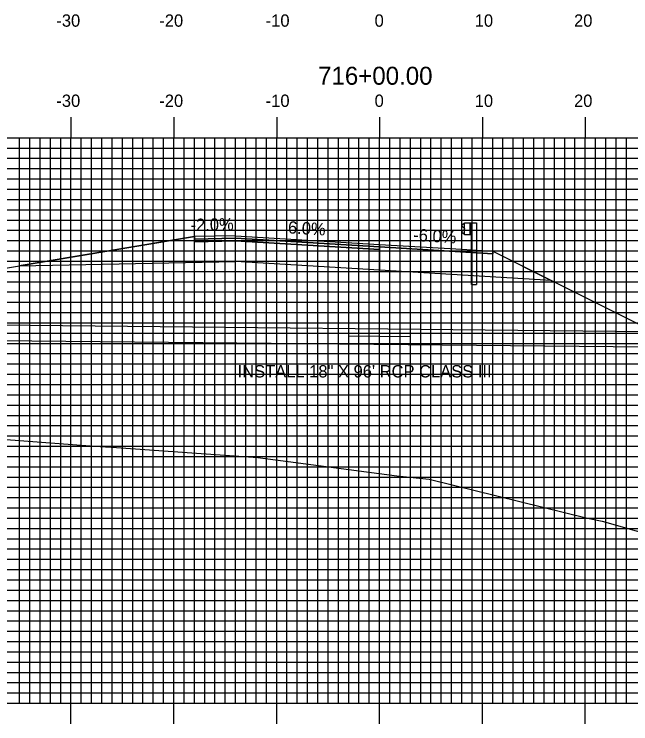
# Model space of a CAD drawing. Extents: x 856478 to 856821, y 364366 to 364586.
# Drawn here: x 856607.8 to 856667.7, y 364448.1 to 364517.1 of the extents above; entities that cross this region are included whole.
import ezdxf

# ---------------------------------------------------------------- set-up
doc = ezdxf.new("R2010")
doc.units = 0
for name, color, linetype in [('ANNOTATION', 7, 'Continuous'), ('D_Drainage_Culvert', 7, 'Continuous'), ('D_Drainage_Text', 7, 'Continuous'), ('D_Guardrail_Beam_Rt', 7, 'Continuous'), ('D_Roadway_Edge_Shoulder', 7, 'Continuous'), ('D_Roadway_Edge_TW', 7, 'Continuous'), ('D_Roadway_Pavement', 7, 'Continuous'), ('D_Roadway_SlopeLines', 7, 'Continuous'), ('D_Roadway_SubGrade', 7, 'Continuous'), ('H_V ANNOTATION', 7, 'Continuous'), ('MAJOR', 7, 'Continuous'), ('MINOR', 7, 'Continuous'), ('S_Roadway_Centerline', 7, 'Continuous')]:
    doc.layers.add(name, color=color, linetype=linetype)

msp = doc.modelspace()

# ---------------------------------------------------------------- linework, layer by layer
at = {"layer": 'ANNOTATION'}
msp.add_line((856582.323, 364488.315), (856625.309, 364495.474), dxfattribs=at)
at = {"layer": 'D_Drainage_Culvert'}
for p, q in [((856577.032, 364487.162), (856673.027, 364486.202)), ((856577.017, 364485.662), (856673.012, 364484.702)), ((856640.309, 364485.817), (856646.309, 364485.757))]:
    msp.add_line(p, q, dxfattribs=at)
at = {"layer": 'D_Guardrail_Beam_Rt'}
for p, q in [((856651.49, 364496.712), (856651.347, 364496.612)), ((856651.347, 364496.469), (856651.542, 364496.333)), ((856651.58, 364496.734), (856651.506, 364496.719)), ((856651.58, 364496.817), (856652.268, 364496.817)), ((856651.58, 364495.65), (856651.58, 364496.817)), ((856652.101, 364496.817), (856652.101, 364495.65)), ((856652.205, 364496.817), (856652.205, 364495.65)), ((856652.268, 364496.817), (856652.738, 364496.817)), ((856652.268, 364496.817), (856652.268, 364495.65)), ((856652.738, 364496.817), (856652.738, 364490.817)), ((856651.542, 364496.134), (856651.347, 364495.998)), ((856651.347, 364495.855), (856651.49, 364495.755)), ((856651.506, 364495.748), (856651.58, 364495.734)), ((856651.576, 364496.269), (856651.576, 364496.199)), ((856652.268, 364495.65), (856651.58, 364495.65)), ((856652.247, 364490.817), (856652.247, 364495.65)), ((856652.247, 364490.817), (856652.738, 364490.817))]:
    msp.add_line(p, q, dxfattribs=at)
for centre, major_axis, start_param, end_param in [((856651.397, 364496.541), (-0.0877, 0), 5.323254, 7.243116), ((856651.514, 364496.678), (-0.0417, 0), 4.907132, 5.323254), ((856651.497, 364496.269), (0.0789, 0), 0, 0.959931), ((856651.397, 364495.927), (-0.0877, 0), 5.323254, 7.243116), ((856651.514, 364495.789), (-0.0417, 0), 0.959931, 1.376053), ((856651.497, 364496.199), (0.0789, 0), 5.323254, 6.283185)]:
    msp.add_ellipse(centre, major_axis=major_axis, ratio=0.995501, start_param=start_param, end_param=end_param, dxfattribs=at)
at = {"layer": 'D_Roadway_Edge_Shoulder'}
for points in [[(856629.309, 364495.554), (856625.309, 364495.474), (856625.309, 364495.224), (856629.309, 364495.304)], [(856643.309, 364494.714), (856651.309, 364494.234), (856651.309, 364494.234), (856654.309, 364494.054), (856654.309, 364493.804), (856643.309, 364494.464)]]:
    msp.add_lwpolyline(points, close=True, dxfattribs=at)
at = {"layer": 'D_Roadway_Edge_TW'}
msp.add_lwpolyline([(856629.309, 364495.554), (856643.309, 364494.714), (856643.309, 364494.464), (856629.309, 364495.304)], close=True, dxfattribs=at)
at = {"layer": 'D_Roadway_Pavement'}
for points in [[(856629.309, 364495.304), (856625.309, 364495.224), (856625.309, 364494.974), (856629.309, 364495.054)], [(856629.309, 364495.304), (856643.309, 364494.464), (856643.309, 364494.214), (856629.309, 364495.054)]]:
    msp.add_lwpolyline(points, close=True, dxfattribs=at)
msp.add_lwpolyline([(856643.309, 364494.464), (856643.309, 364494.214)], dxfattribs=at)
msp.add_lwpolyline([(856643.309, 364494.464), (856643.309, 364494.214)], dxfattribs=at)
at = {"layer": 'D_Roadway_SlopeLines'}
msp.add_lwpolyline([(856654.309, 364494.054), (856726.292, 364458.062)], dxfattribs=at)
at = {"layer": 'D_Roadway_SubGrade'}
for points in [[(856629.309, 364495.054), (856625.309, 364494.974), (856625.309, 364495.224), (856625.309, 364495.474), (856608.264, 364492.633), (856629.309, 364493.054)], [(856629.309, 364495.054), (856643.309, 364494.214), (856643.309, 364492.214), (856629.309, 364493.054)], [(856643.309, 364494.214), (856643.309, 364494.464), (856654.309, 364493.804), (856654.309, 364494.054), (856659.991, 364491.213), (856643.309, 364492.214)]]:
    msp.add_lwpolyline(points, close=True, dxfattribs=at)
at = {"layer": 'MAJOR'}
for p, q in [((856613.309, 364507.086), (856613.309, 364505.082)), ((856623.309, 364507.086), (856623.309, 364505.082)), ((856633.309, 364507.086), (856633.309, 364505.082)), ((856643.309, 364507.086), (856643.309, 364505.082)), ((856653.309, 364507.086), (856653.309, 364505.082)), ((856663.309, 364507.086), (856663.309, 364505.082)), ((856503.309, 364505.082), (856783.309, 364505.082)), ((856503.309, 364505.082), (856783.309, 364505.082)), ((856613.309, 364450.082), (856613.309, 364505.082)), ((856623.309, 364450.082), (856623.309, 364505.082)), ((856633.309, 364450.082), (856633.309, 364505.082)), ((856643.309, 364450.082), (856643.309, 364505.082)), ((856653.309, 364450.082), (856653.309, 364505.082)), ((856663.309, 364450.082), (856663.309, 364505.082)), ((856503.309, 364500.082), (856783.309, 364500.082)), ((856503.309, 364495.082), (856783.309, 364495.082)), ((856503.309, 364490.082), (856783.309, 364490.082)), ((856503.309, 364485.082), (856783.309, 364485.082)), ((856503.309, 364480.082), (856783.309, 364480.082)), ((856503.309, 364475.082), (856783.309, 364475.082)), ((856503.309, 364470.082), (856783.309, 364470.082)), ((856503.309, 364465.082), (856783.309, 364465.082)), ((856503.309, 364460.082), (856783.309, 364460.082)), ((856503.309, 364455.082), (856783.309, 364455.082)), ((856503.309, 364450.082), (856783.309, 364450.082)), ((856503.309, 364450.082), (856783.309, 364450.082)), ((856613.309, 364448.078), (856613.309, 364450.082)), ((856623.309, 364448.078), (856623.309, 364450.082)), ((856633.309, 364448.078), (856633.309, 364450.082)), ((856643.309, 364448.078), (856643.309, 364450.082)), ((856653.309, 364448.078), (856653.309, 364450.082)), ((856663.309, 364448.078), (856663.309, 364450.082))]:
    msp.add_line(p, q, dxfattribs=at)
at = {"layer": 'MINOR'}
for p, q in [((856608.309, 364450.082), (856608.309, 364505.082)), ((856609.309, 364450.082), (856609.309, 364505.082)), ((856610.309, 364450.082), (856610.309, 364505.082)), ((856611.309, 364450.082), (856611.309, 364505.082)), ((856612.309, 364450.082), (856612.309, 364505.082)), ((856614.309, 364450.082), (856614.309, 364505.082)), ((856615.309, 364450.082), (856615.309, 364505.082)), ((856616.309, 364450.082), (856616.309, 364505.082)), ((856617.309, 364450.082), (856617.309, 364505.082)), ((856618.309, 364450.082), (856618.309, 364505.082)), ((856619.309, 364450.082), (856619.309, 364505.082)), ((856620.309, 364450.082), (856620.309, 364505.082)), ((856621.309, 364450.082), (856621.309, 364505.082)), ((856622.309, 364450.082), (856622.309, 364505.082)), ((856624.309, 364450.082), (856624.309, 364505.082)), ((856625.309, 364450.082), (856625.309, 364505.082)), ((856626.309, 364450.082), (856626.309, 364505.082)), ((856627.309, 364450.082), (856627.309, 364505.082)), ((856628.309, 364450.082), (856628.309, 364505.082)), ((856629.309, 364450.082), (856629.309, 364505.082)), ((856630.309, 364450.082), (856630.309, 364505.082)), ((856631.309, 364450.082), (856631.309, 364505.082)), ((856632.309, 364450.082), (856632.309, 364505.082)), ((856634.309, 364450.082), (856634.309, 364505.082)), ((856635.309, 364450.082), (856635.309, 364505.082)), ((856636.309, 364450.082), (856636.309, 364505.082)), ((856637.309, 364450.082), (856637.309, 364505.082)), ((856638.309, 364450.082), (856638.309, 364505.082)), ((856639.309, 364450.082), (856639.309, 364505.082)), ((856640.309, 364450.082), (856640.309, 364505.082)), ((856641.309, 364450.082), (856641.309, 364505.082)), ((856642.309, 364450.082), (856642.309, 364505.082)), ((856644.309, 364450.082), (856644.309, 364505.082)), ((856645.309, 364450.082), (856645.309, 364505.082)), ((856646.309, 364450.082), (856646.309, 364505.082)), ((856647.309, 364450.082), (856647.309, 364505.082)), ((856648.309, 364450.082), (856648.309, 364505.082)), ((856649.309, 364450.082), (856649.309, 364505.082)), ((856650.309, 364450.082), (856650.309, 364505.082)), ((856651.309, 364450.082), (856651.309, 364505.082)), ((856652.309, 364450.082), (856652.309, 364505.082)), ((856654.309, 364450.082), (856654.309, 364505.082)), ((856655.309, 364450.082), (856655.309, 364505.082)), ((856656.309, 364450.082), (856656.309, 364505.082)), ((856657.309, 364450.082), (856657.309, 364505.082)), ((856658.309, 364450.082), (856658.309, 364505.082)), ((856659.309, 364450.082), (856659.309, 364505.082)), ((856660.309, 364450.082), (856660.309, 364505.082)), ((856661.309, 364450.082), (856661.309, 364505.082)), ((856662.309, 364450.082), (856662.309, 364505.082)), ((856664.309, 364450.082), (856664.309, 364505.082)), ((856665.309, 364450.082), (856665.309, 364505.082)), ((856666.309, 364450.082), (856666.309, 364505.082)), ((856667.309, 364450.082), (856667.309, 364505.082)), ((856503.309, 364504.082), (856783.309, 364504.082)), ((856503.309, 364503.082), (856783.309, 364503.082)), ((856503.309, 364502.082), (856783.309, 364502.082)), ((856503.309, 364501.082), (856783.309, 364501.082)), ((856503.309, 364499.082), (856783.309, 364499.082)), ((856503.309, 364498.082), (856783.309, 364498.082)), ((856503.309, 364497.082), (856783.309, 364497.082)), ((856503.309, 364496.082), (856783.309, 364496.082)), ((856503.309, 364494.082), (856783.309, 364494.082)), ((856503.309, 364493.082), (856783.309, 364493.082)), ((856503.309, 364492.082), (856783.309, 364492.082)), ((856503.309, 364491.082), (856783.309, 364491.082)), ((856503.309, 364489.082), (856783.309, 364489.082)), ((856503.309, 364488.082), (856783.309, 364488.082)), ((856503.309, 364487.082), (856783.309, 364487.082)), ((856503.309, 364486.082), (856783.309, 364486.082)), ((856503.309, 364484.082), (856783.309, 364484.082)), ((856503.309, 364483.082), (856783.309, 364483.082)), ((856503.309, 364482.082), (856783.309, 364482.082)), ((856503.309, 364481.082), (856783.309, 364481.082)), ((856503.309, 364479.082), (856783.309, 364479.082)), ((856503.309, 364478.082), (856783.309, 364478.082)), ((856503.309, 364477.082), (856783.309, 364477.082)), ((856503.309, 364476.082), (856783.309, 364476.082)), ((856503.309, 364474.082), (856783.309, 364474.082)), ((856503.309, 364473.082), (856783.309, 364473.082)), ((856503.309, 364472.082), (856783.309, 364472.082)), ((856503.309, 364471.082), (856783.309, 364471.082)), ((856503.309, 364469.082), (856783.309, 364469.082)), ((856503.309, 364468.082), (856783.309, 364468.082)), ((856503.309, 364467.082), (856783.309, 364467.082)), ((856503.309, 364466.082), (856783.309, 364466.082)), ((856503.309, 364464.082), (856783.309, 364464.082)), ((856503.309, 364463.082), (856783.309, 364463.082)), ((856503.309, 364462.082), (856783.309, 364462.082)), ((856503.309, 364461.082), (856783.309, 364461.082)), ((856503.309, 364459.082), (856783.309, 364459.082)), ((856503.309, 364458.082), (856783.309, 364458.082)), ((856503.309, 364457.082), (856783.309, 364457.082)), ((856503.309, 364456.082), (856783.309, 364456.082)), ((856503.309, 364454.082), (856783.309, 364454.082)), ((856503.309, 364453.082), (856783.309, 364453.082)), ((856503.309, 364452.082), (856783.309, 364452.082)), ((856503.309, 364451.082), (856783.309, 364451.082))]:
    msp.add_line(p, q, dxfattribs=at)
at = {"layer": 'S_Roadway_Centerline'}
msp.add_lwpolyline([(856603.112, 364476.009), (856615.61, 364475.069), (856617.717, 364474.957), (856631.467, 364473.987), (856644.986, 364472.187), (856648.122, 364471.866), (856663.525, 364468.096), (856664.964, 364467.792), (856678.414, 364463.963), (856685.009, 364462.253), (856697.732, 364459.661), (856702.217, 364458.811), (856713.926, 364458.579), (856720.37, 364458.394), (856730.267, 364457.84), (856738.35, 364457.682), (856746.187, 364457.472), (856755.537, 364457.448), (856762.711, 364457.427), (856774.227, 364457.36), (856779.079, 364457.224), (856783.309, 364457.335)], dxfattribs=at)

# ---------------------------------------------------------------- texts
at = {"layer": 'ANNOTATION'}
for s, rotation, p in [('-2.0%', 1.14576, (856624.945, 364496)), ('6.0%', 356.56637, (856634.376, 364495.784)), ('-6.0%', 356.56637, (856646.555, 364495.054))]:
    msp.add_text(s, height=1.2, rotation=rotation, dxfattribs=at).set_placement(p)
at = {"layer": 'D_Drainage_Text'}
msp.add_text('INSTALL 18" X 96\' RCP CLASS III', height=1.2, dxfattribs=at).set_placement((856629.509, 364481.767))
at = {"layer": 'H_V ANNOTATION'}
for s, height, p in [('-30', 1.2, (856611.886, 364515.882)), ('-20', 1.2, (856621.896, 364515.882)), ('-10', 1.2, (856632.239, 364515.882)), ('0', 1.2, (856642.827, 364515.882)), ('10', 1.2, (856652.56, 364515.882)), ('20', 1.2, (856662.217, 364515.882)), ('716+00.00', 1.75, (856637.332, 364510.238)), ('-30', 1.2, (856611.886, 364508.082)), ('-20', 1.2, (856621.896, 364508.082)), ('-10', 1.2, (856632.239, 364508.082)), ('0', 1.2, (856642.827, 364508.082)), ('10', 1.2, (856652.56, 364508.082)), ('20', 1.2, (856662.217, 364508.082))]:
    msp.add_text(s, height=height, dxfattribs=at).set_placement(p)

doc.saveas('drawing.dxf')
